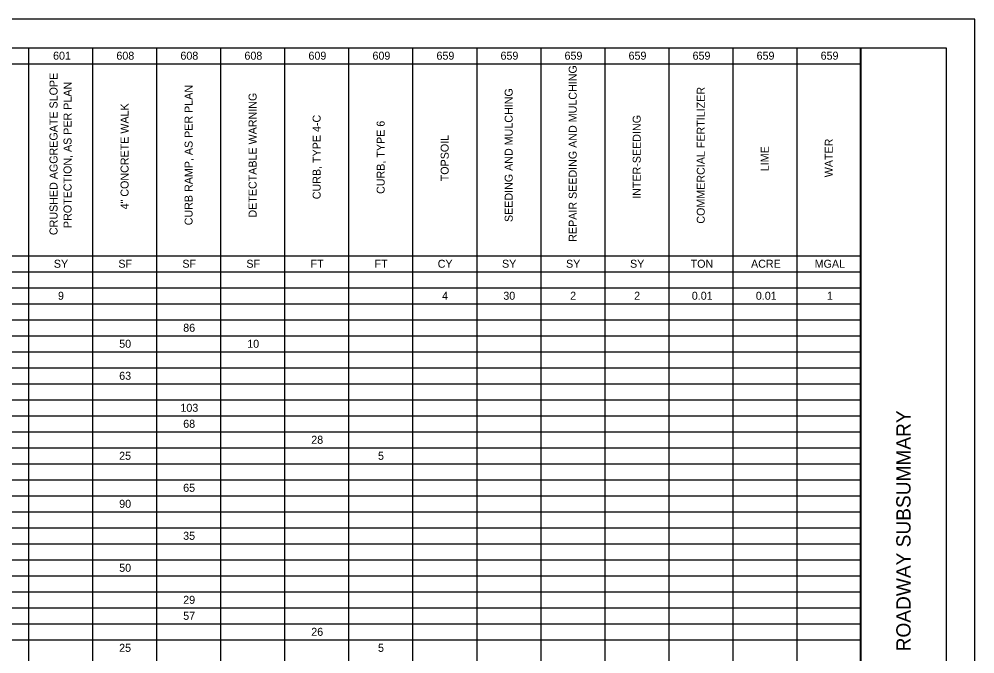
# Model space of a CAD drawing. Extents: x 0 to 34, y 0 to 22.
# Drawn here: x 17.28 to 34, y 10.89 to 22 of the extents above; entities that cross this region are included whole.
import ezdxf

# ---------------------------------------------------------------- set-up
doc = ezdxf.new("R2010")
doc.units = 0
for name, color, linetype in [('SH_Border', 7, 'Continuous'), ('SH_Cut_Line', 7, 'Continuous'), ('SH_Data', 7, 'Continuous'), ('SH_Text', 7, 'Continuous')]:
    doc.layers.add(name, color=color, linetype=linetype)

msp = doc.modelspace()

# ---------------------------------------------------------------- linework, layer by layer
at = {"layer": 'SH_Border'}
msp.add_line((32, 0.5), (32, 21.5), dxfattribs=at)
msp.add_lwpolyline([(1.5, 21.5), (33.5, 21.5), (33.5, 0.5), (1.5, 0.5)], close=True, dxfattribs=at)
at = {"layer": 'SH_Cut_Line'}
msp.add_lwpolyline([(0, 0), (34, 0), (34, 22), (0, 22)], close=True, dxfattribs=at)
at = {"layer": 'SH_Text'}
for p, q in [((1.5, 21.5), (32.004, 21.5)), ((17.444, 21.5), (17.444, 0.5)), ((18.564, 21.5), (18.564, 0.5)), ((19.684, 21.5), (19.684, 0.5)), ((20.804, 21.5), (20.804, 0.5)), ((21.924, 21.5), (21.924, 0.5)), ((23.044, 21.5), (23.044, 0.5)), ((24.164, 21.5), (24.164, 0.5)), ((25.284, 21.5), (25.284, 0.5)), ((26.404, 21.5), (26.404, 0.5)), ((27.524, 21.5), (27.524, 0.5)), ((28.644, 21.5), (28.644, 0.5)), ((29.764, 21.5), (29.764, 0.5)), ((30.884, 21.5), (30.884, 0.5)), ((32.004, 21.5), (32.004, 0.5)), ((8.484, 21.22), (32.004, 21.22)), ((8.484, 17.86), (32.004, 17.86)), ((1.5, 17.58), (32.004, 17.58)), ((1.5, 17.3), (32.004, 17.3)), ((1.5, 17.02), (32.004, 17.02)), ((1.5, 16.74), (32.004, 16.74)), ((1.5, 16.46), (32.004, 16.46)), ((1.5, 16.18), (32.004, 16.18)), ((1.5, 15.9), (32.004, 15.9)), ((1.5, 15.62), (32.004, 15.62)), ((1.5, 15.34), (32.004, 15.34)), ((1.5, 15.06), (32.004, 15.06)), ((1.5, 14.78), (32.004, 14.78)), ((1.5, 14.5), (32.004, 14.5)), ((1.5, 14.22), (32.004, 14.22)), ((1.5, 13.94), (32.004, 13.94)), ((1.5, 13.66), (32.004, 13.66)), ((1.5, 13.38), (32.004, 13.38)), ((1.5, 13.1), (32.004, 13.1)), ((1.5, 12.82), (32.004, 12.82)), ((1.5, 12.54), (32.004, 12.54)), ((1.5, 12.26), (32.004, 12.26)), ((1.5, 11.98), (32.004, 11.98)), ((1.5, 11.7), (32.004, 11.7)), ((1.5, 11.42), (32.004, 11.42)), ((1.5, 11.14), (32.004, 11.14))]:
    msp.add_line(p, q, dxfattribs=at)

# ---------------------------------------------------------------- texts
at = {"layer": 'SH_Data'}
msp.add_text('ROADWAY SUBSUMMARY', height=0.25, rotation=90, dxfattribs=at).set_placement((32.875, 10.938))
at = {"layer": 'SH_Text'}
for s, p in [('601', (17.873, 21.29)), ('608', (18.981, 21.29)), ('608', (20.101, 21.29)), ('608', (21.221, 21.29)), ('609', (22.341, 21.29)), ('609', (23.461, 21.29)), ('659', (24.581, 21.29)), ('659', (25.701, 21.29)), ('659', (26.821, 21.29)), ('659', (27.941, 21.29)), ('659', (29.061, 21.29)), ('659', (30.181, 21.29)), ('659', (31.301, 21.29)), ('SY', (17.887, 17.65)), ('SF', (19.015, 17.65)), ('SF', (20.135, 17.65)), ('SF', (21.255, 17.65)), ('FT', (22.378, 17.65)), ('FT', (23.498, 17.65)), ('CY', (24.602, 17.65)), ('SY', (25.727, 17.65)), ('SY', (26.847, 17.65)), ('SY', (27.967, 17.65)), ('TON', (29.027, 17.65)), ('ACRE', (30.084, 17.65)), ('MGAL', (31.197, 17.65)), ('9', (17.959, 17.09)), ('4', (24.679, 17.09)), ('30', (25.75, 17.09)), ('2', (26.919, 17.09)), ('2', (28.039, 17.09)), ('0.01', (29.048, 17.09)), ('0.01', (30.168, 17.09)), ('1', (31.411, 17.09)), ('86', (20.15, 16.53)), ('50', (19.03, 16.25)), ('10', (21.27, 16.25)), ('63', (19.03, 15.69)), ('103', (20.101, 15.13)), ('68', (20.15, 14.85)), ('28', (22.39, 14.57)), ('25', (19.029, 14.29)), ('5', (23.558, 14.29)), ('65', (20.149, 13.73)), ('90', (19.03, 13.45)), ('35', (20.149, 12.89)), ('50', (19.03, 12.33)), ('29', (20.15, 11.77)), ('57', (20.15, 11.49)), ('26', (22.39, 11.21)), ('25', (19.029, 10.93)), ('5', (23.558, 10.93))]:
    msp.add_text(s, height=0.14, dxfattribs=at).set_placement(p)
for s, p in [('REPAIR SEEDING AND MULCHING', (27.034, 18.104)), ('CRUSHED AGGREGATE SLOPE ', (17.951, 18.221)), ('PROTECTION, AS PER PLAN', (18.196, 18.344)), ('CURB RAMP, AS PER PLAN', (20.314, 18.393)), ('SEEDING AND MULCHING', (25.914, 18.45)), ('COMMERCIAL FERTILIZER', (29.274, 18.421)), ('DETECTABLE WARNING', (21.434, 18.528)), ('4" CONCRETE WALK', (19.194, 18.671)), ('CURB, TYPE 4-C', (22.554, 18.849)), ('INTER-SEEDING', (28.154, 18.856)), ('CURB, TYPE 6', (23.674, 18.942)), ('TOPSOIL', (24.794, 19.163)), ('WATER', (31.514, 19.233)), ('LIME', (30.394, 19.339))]:
    msp.add_text(s, height=0.14, rotation=90, dxfattribs=at).set_placement(p)

doc.saveas('drawing.dxf')
